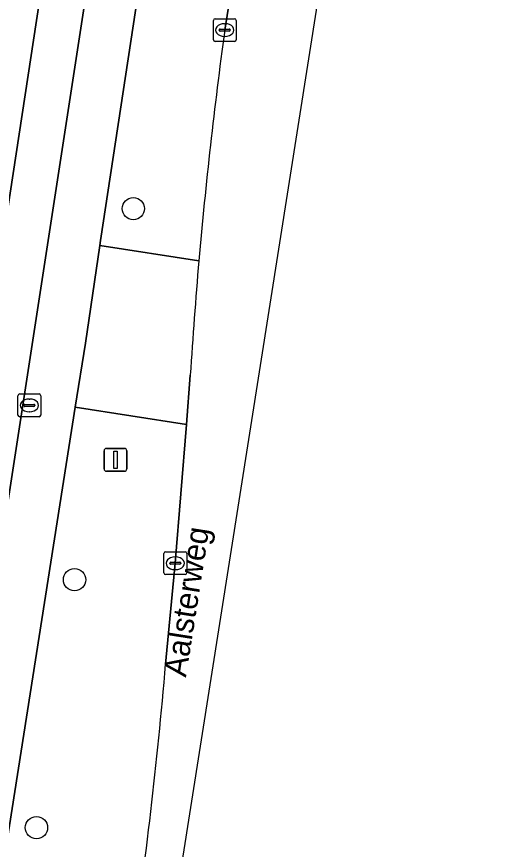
# Model space of a CAD drawing. Extents: x 161090 to 161692, y 379509 to 380907.
# Drawn here: x 161615.99 to 161637.79, y 380358.19 to 380394.7 of the extents above; entities that cross this region are included whole.
import ezdxf

# ---------------------------------------------------------------- set-up
doc = ezdxf.new("R2010")
doc.units = 0
for name, color, linetype in [('IMGEO_Berm_groen', 7, 'Continuous'), ('IMGEO_Boom', 7, 'Continuous'), ('IMGEO_Fietspad_gesloten', 7, 'Continuous'), ('IMGEO_Groenvoorziening', 7, 'Continuous'), ('IMGEO_Kolk', 7, 'Continuous'), ('IMGEO_Lichtmast', 7, 'Continuous'), ('IMGEO_Openbare_ruimte_label', 7, 'Continuous'), ('IMGEO_Rijbaan_lokaal_open', 7, 'Continuous'), ('IMGEO_Rijbaan_regionaal_gesloten', 7, 'Continuous'), ('IMGEO_Rioolput', 7, 'Continuous'), ('IMGEO_Voetpad_open', 7, 'Continuous')]:
    doc.layers.add(name, color=color, linetype=linetype)

msp = doc.modelspace()

# ---------------------------------------------------------------- linework, layer by layer
at = {"layer": 'IMGEO_Berm_groen'}
for points in [[(161629.075, 380419.224), (161625.649, 380423.882), (161625.07, 380420.051), (161622.852, 380405.923), (161622.43, 380403.035), (161619.668, 380384.881), (161619.636, 380384.663), (161623.975, 380383.998)], [(161625.109, 380394.111), (161628.145, 380413.237), (161629.075, 380419.224)], [(161622.517, 380366.313), (161622.941, 380370.736), (161623.428, 380376.818), (161618.561, 380377.574), (161615.522, 380358.208), (161614.175, 380349.387), (161612.498, 380338.392), (161608.177, 380310.609)]]:
    msp.add_lwpolyline(points, dxfattribs=at)
for centre, radius, start, end in [((161827.799, 380366.263), 204.594, 172.17691, 175.02706), ((161415.48, 380383.836), 207.778, 351.58062, 355.1621)]:
    msp.add_arc(centre, radius, start, end, dxfattribs=at)
at = {"layer": 'IMGEO_Boom'}
for centre in [(161621.103, 380386.282), (161618.528, 380370.013), (161616.859, 380359.142)]:
    msp.add_circle(centre, 0.489, dxfattribs=at)
at = {"layer": 'IMGEO_Fietspad_gesloten'}
for points in [[(161608.177, 380310.609), (161612.498, 380338.392), (161614.175, 380349.387), (161615.522, 380358.208), (161618.561, 380377.574), (161619.001, 380380.379), (161619.636, 380384.663), (161619.668, 380384.881), (161622.43, 380403.035), (161622.852, 380405.923), (161625.07, 380420.051), (161625.649, 380423.882), (161627.147, 380433.8), (161627.322, 380434.961), (161629.991, 380452.28)], [(161623.371, 380423.923), (161622.87, 380420.7), (161611.943, 380349.647), (161610.562, 380340.668), (161610.539, 380340.52), (161605.928, 380311.015)]]:
    msp.add_lwpolyline(points, dxfattribs=at)
at = {"layer": 'IMGEO_Groenvoorziening'}
msp.add_lwpolyline([(161621.441, 380424.641), (161613.791, 380425.771), (161607.762, 380390.596), (161607.104, 380385.838), (161615.349, 380384.57)], close=True, dxfattribs=at)
at = {"layer": 'IMGEO_Kolk'}
for p, q in [((161624.608, 380393.685), (161624.608, 380394.537)), ((161624.683, 380394.611), (161625.535, 380394.611)), ((161625.609, 380394.537), (161625.609, 380393.685)), ((161624.867, 380394.105), (161624.867, 380394.117)), ((161624.91, 380394.154), (161625.308, 380394.154)), ((161625.096, 380394.391), (161625.121, 380394.391)), ((161625.351, 380394.117), (161625.351, 380394.105)), ((161625.305, 380394.068), (161624.907, 380394.068)), ((161625.119, 380393.831), (161625.094, 380393.831)), ((161625.535, 380393.611), (161624.683, 380393.611)), ((161622.44, 380370.31), (161622.44, 380371.162)), ((161622.515, 380371.236), (161623.367, 380371.236)), ((161623.441, 380371.162), (161623.441, 380370.31)), ((161622.699, 380370.73), (161622.699, 380370.742)), ((161622.742, 380370.779), (161623.14, 380370.779)), ((161622.928, 380371.016), (161622.953, 380371.016)), ((161623.183, 380370.742), (161623.183, 380370.73)), ((161623.137, 380370.693), (161622.739, 380370.693)), ((161622.951, 380370.456), (161622.926, 380370.456)), ((161623.367, 380370.236), (161622.515, 380370.236))]:
    msp.add_line(p, q, dxfattribs=at)
for points in [[(161624.608, 380393.685), (161624.608, 380394.537)], [(161624.683, 380394.611), (161625.535, 380394.611)], [(161625.609, 380394.537), (161625.609, 380393.685)], [(161625.535, 380393.611), (161624.683, 380393.611)], [(161622.44, 380370.31), (161622.44, 380371.162)], [(161622.515, 380371.236), (161623.367, 380371.236)], [(161623.441, 380371.162), (161623.441, 380370.31)], [(161623.367, 380370.236), (161622.515, 380370.236)]]:
    msp.add_lwpolyline(points, dxfattribs=at)
for centre, radius, start, end in [((161624.685, 380394.535), 0.0765, 91.552, 178.448), ((161624.685, 380394.535), 0.0765, 91.552, 178.448), ((161625.533, 380394.535), 0.0765, 1.552, 88.448), ((161625.533, 380394.535), 0.0765, 1.552, 88.448), ((161624.907, 380394.114), 0.0403, 85.8775, 175.7526), ((161624.904, 380394.104), 0.0366, 178.938, 274.7102), ((161625.308, 380394.111), 0.043, 264.8664, 352.4533), ((161625.312, 380394.116), 0.0386, 1.7309, 96.639), ((161624.685, 380393.687), 0.0765, 181.552, 268.448), ((161624.685, 380393.687), 0.0765, 181.552, 268.448), ((161625.533, 380393.687), 0.0765, 271.552, 358.448), ((161625.533, 380393.687), 0.0765, 271.552, 358.448), ((161622.517, 380371.16), 0.0765, 91.552, 178.448), ((161622.517, 380371.16), 0.0765, 91.552, 178.448), ((161623.365, 380371.16), 0.0765, 1.552, 88.448), ((161623.365, 380371.16), 0.0765, 1.552, 88.448), ((161622.739, 380370.739), 0.0403, 85.8775, 175.7526), ((161622.736, 380370.729), 0.0366, 178.938, 274.7102), ((161623.14, 380370.736), 0.043, 264.8664, 352.4533), ((161623.144, 380370.741), 0.0386, 1.7309, 96.639), ((161622.517, 380370.312), 0.0765, 181.552, 268.448), ((161622.517, 380370.312), 0.0765, 181.552, 268.448), ((161623.365, 380370.312), 0.0765, 271.552, 358.448), ((161623.365, 380370.312), 0.0765, 271.552, 358.448)]:
    msp.add_arc(centre, radius, start, end, dxfattribs=at)
for centre, major_axis, ratio, start_param, end_param in [((161625.095, 380394.111), (-0.387, 0.002), 0.722429, 4.712389, 7.853982), ((161625.12, 380394.111), (-0.39, 0.002), 0.717154, 1.570796, 4.712389), ((161622.927, 380370.736), (-0.387, 0.002), 0.722429, 4.712389, 7.853982), ((161622.952, 380370.736), (-0.39, 0.002), 0.717154, 1.570796, 4.712389)]:
    msp.add_ellipse(centre, major_axis=major_axis, ratio=ratio, start_param=start_param, end_param=end_param, dxfattribs=at)
at = {"layer": 'IMGEO_Lichtmast'}
for p, q in [((161619.822, 380374.868), (161619.822, 380375.668)), ((161619.822, 380375.668), (161619.822, 380374.868)), ((161619.922, 380375.768), (161620.712, 380375.768)), ((161620.712, 380375.768), (161619.922, 380375.768)), ((161620.812, 380375.668), (161620.812, 380374.868)), ((161620.812, 380374.868), (161620.812, 380375.668)), ((161620.712, 380374.768), (161619.922, 380374.768)), ((161619.922, 380374.768), (161620.712, 380374.768))]:
    msp.add_line(p, q, dxfattribs=at)
msp.add_lwpolyline([(161620.242, 380375.643), (161620.392, 380375.643), (161620.392, 380374.893), (161620.242, 380374.893), (161620.242, 380375.643)], dxfattribs=at)
for centre, start, end in [((161619.922, 380375.668), 90, 180), ((161619.922, 380375.668), 90, 180), ((161620.712, 380375.668), 0, 90), ((161620.712, 380375.668), 360, 90), ((161619.922, 380374.868), 180, 270), ((161619.922, 380374.868), 180, 270), ((161620.712, 380374.868), 270, 0), ((161620.712, 380374.868), 270, 0)]:
    msp.add_arc(centre, 0.1, start, end, dxfattribs=at)
at = {"layer": 'IMGEO_Rijbaan_lokaal_open'}
msp.add_lwpolyline([(161623.975, 380383.998), (161619.636, 380384.663), (161619.001, 380380.379), (161618.561, 380377.574), (161623.428, 380376.818), (161623.6, 380378.975)], dxfattribs=at)
msp.add_arc((161826.918, 380366.321), 203.712, 175.02205, 176.43878, dxfattribs=at)
at = {"layer": 'IMGEO_Rijbaan_regionaal_gesloten'}
for points in [[(161636.306, 380466.142), (161635.833, 380462.876), (161635.828, 380462.842), (161635.301, 380459.435), (161635.052, 380457.763), (161634.852, 380456.537), (161634.353, 380453.162), (161633.68, 380448.786), (161631.601, 380435.492), (161631.236, 380433.142), (161629.075, 380419.224), (161628.145, 380413.237), (161625.109, 380394.111)], [(161637.681, 380451.575), (161637.794, 380452.518), (161634.353, 380453.162), (161633.68, 380448.786), (161631.601, 380435.492), (161631.236, 380433.142), (161629.075, 380419.224), (161628.145, 380413.237), (161625.109, 380394.111)], [(161478.643, 379510.393), (161478.776, 379510.36), (161479.619, 379510.148), (161483.049, 379509.288), (161487.608, 379545.266), (161501.181, 379627.196), (161502.416, 379652.496), (161532.835, 379804.993), (161534.038, 379811.023), (161544.184, 379852.271), (161580.241, 380085.167), (161590.693, 380150.921), (161608.302, 380261.697), (161622.126, 380350.531), (161633.798, 380424.683), (161634.415, 380428.72), (161637.543, 380449.191)], [(161526.193, 379784.629), (161525.506, 379781.616), (161520.447, 379758.846), (161518.238, 379748.982), (161517.451, 379745.832), (161513.789, 379733.068), (161513.003, 379729.86), (161510.225, 379718.435), (161506.208, 379697.39), (161502.839, 379678.74), (161498.451, 379652.791), (161502.568, 379653.26), (161532.835, 379804.993), (161534.038, 379811.023), (161544.184, 379852.271), (161580.241, 380085.167), (161590.693, 380150.921), (161608.302, 380261.697), (161622.126, 380350.531), (161633.798, 380424.683), (161634.415, 380428.72), (161637.543, 380449.191)], [(161623.6, 380378.975), (161623.428, 380376.818), (161622.941, 380370.736), (161622.517, 380366.313)], [(161623.6, 380378.975), (161623.428, 380376.818), (161622.941, 380370.736), (161622.517, 380366.313)]]:
    msp.add_lwpolyline(points, dxfattribs=at)
for centre, radius, start, end in [((161827.799, 380366.263), 204.594, 172.17691, 175.02706), ((161827.799, 380366.263), 204.594, 172.17691, 175.02706), ((161826.918, 380366.321), 203.712, 175.02205, 176.43878), ((161826.918, 380366.321), 203.712, 175.02205, 176.43878), ((161415.48, 380383.836), 207.778, 351.58062, 355.1621), ((161415.48, 380383.836), 207.778, 351.58062, 355.1621)]:
    msp.add_arc(centre, radius, start, end, dxfattribs=at)
at = {"layer": 'IMGEO_Rioolput'}
for p, q in [((161616.049, 380377.23), (161616.049, 380378.082)), ((161616.124, 380378.156), (161616.976, 380378.156)), ((161617.05, 380378.082), (161617.05, 380377.23)), ((161616.308, 380377.65), (161616.308, 380377.662)), ((161616.351, 380377.699), (161616.749, 380377.699)), ((161616.537, 380377.936), (161616.562, 380377.936)), ((161616.792, 380377.662), (161616.792, 380377.65)), ((161616.746, 380377.613), (161616.348, 380377.613)), ((161616.56, 380377.376), (161616.535, 380377.376)), ((161616.976, 380377.156), (161616.124, 380377.156))]:
    msp.add_line(p, q, dxfattribs=at)
for points in [[(161616.049, 380377.23), (161616.049, 380378.082)], [(161616.124, 380378.156), (161616.976, 380378.156)], [(161617.05, 380378.082), (161617.05, 380377.23)], [(161616.976, 380377.156), (161616.124, 380377.156)]]:
    msp.add_lwpolyline(points, dxfattribs=at)
for centre, radius, start, end in [((161616.126, 380378.08), 0.0765, 91.552, 178.448), ((161616.126, 380378.08), 0.0765, 91.552, 178.448), ((161616.974, 380378.08), 0.0765, 1.552, 88.448), ((161616.974, 380378.08), 0.0765, 1.552, 88.448), ((161616.348, 380377.659), 0.0403, 85.8775, 175.7526), ((161616.345, 380377.649), 0.0366, 178.938, 274.7102), ((161616.749, 380377.656), 0.043, 264.8664, 352.4533), ((161616.753, 380377.661), 0.0386, 1.7309, 96.639), ((161616.126, 380377.232), 0.0765, 181.552, 268.448), ((161616.126, 380377.232), 0.0765, 181.552, 268.448), ((161616.974, 380377.232), 0.0765, 271.552, 358.448), ((161616.974, 380377.232), 0.0765, 271.552, 358.448)]:
    msp.add_arc(centre, radius, start, end, dxfattribs=at)
for centre, major_axis, ratio, start_param, end_param in [((161616.536, 380377.656), (-0.387, 0.002), 0.722429, 4.712389, 7.853982), ((161616.561, 380377.656), (-0.39, 0.002), 0.717154, 1.570796, 4.712389)]:
    msp.add_ellipse(centre, major_axis=major_axis, ratio=ratio, start_param=start_param, end_param=end_param, dxfattribs=at)
at = {"layer": 'IMGEO_Voetpad_open'}
msp.add_lwpolyline([(161621.991, 380428.256), (161621.441, 380424.641), (161615.349, 380384.57), (161614.501, 380379.058), (161611.414, 380358.997), (161608.555, 380340.78), (161610.539, 380340.52), (161610.562, 380340.668), (161611.943, 380349.647), (161622.87, 380420.7)], dxfattribs=at)

# ---------------------------------------------------------------- texts
at = {"layer": 'IMGEO_Openbare_ruimte_label'}
msp.add_text('Aalsterweg', height=1, rotation=81.084, dxfattribs=at).set_placement((161623.408, 380365.711))

doc.saveas('drawing.dxf')
